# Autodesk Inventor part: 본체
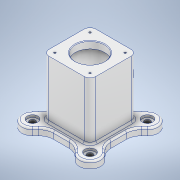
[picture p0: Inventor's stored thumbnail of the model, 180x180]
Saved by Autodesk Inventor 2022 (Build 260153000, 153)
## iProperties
Created: 2022-05
Part Number: 본체
Material: 알루미늄 6061
Document SubType Name: Modeling
Designer: Admin
Mass: 1072.62 g
Surface Area: 876.974 cm^2
Volume: 397.266 cm^3
Density: 2.7 g/cm^3
Appearance: 알루미늄 - 평지
Author: Admin
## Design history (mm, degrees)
sketch "스케치1"
  geometry: L1 (40, 40)-(-40, 40); L2 (-40, 40)-(-40, -40); L3 (-40, -40)-(40, -40); L4 (40, -40)-(40, 40); L5 (40, 40)-(-40, -40); L6 (-40, 40)-(40, -40); 1 further point
  constraints: 12 end point, 2 midpoint, 2 parallel, 1 horizontal, 1 perpendicular
  dimensions: "d0" = 80 distance of L3.end L2.end; "d1" = 80 distance of L2.end L1.end
extrude "돌출1" new body sketch "스케치1" distance "d2" = 110; taper "d3" = 0 deg
sketch "스케치2"
  geometry: L1 (40, 40)-(40, -40) reference; L2 (-40, 40)-(40, 40) reference; L3 (-40, -40)-(-40, 40) reference; L4 (40, -40)-(-40, -40) reference; L5 (-104.238, 0)-(104.238, 0) reference; L6 (0, -104.238)-(0, 104.238) reference; L7 (-23.544, 49)-(23.544, 49); L8 (49, 23.544)-(49, -23.544); L9 (23.544, -49)-(-23.544, -49); L10 (-49, -23.544)-(-49, 23.544); L11 (-49, 49)-(49, -49); L12 (49, 49)-(-49, -49); L13 (-49, 49)-(49, -49); L14 (-49, -49)-(49, 49); L15 (49, 23.544)-(61.728, 36.272); L16 (61.728, -36.272)-(49, -23.544); L17 (36.272, 61.728)-(23.544, 49); L18 (-23.544, 49)-(-36.272, 61.728); L19 (-61.728, 36.272)-(-49, 23.544); L20 (-49, -23.544)-(-61.728, -36.272); L21 (-36.272, -61.728)-(-23.544, -49); L22 (23.544, -49)-(36.272, -61.728); A1 r 18 centre (-49, 49) between (-36.272, 61.728) and (-61.728, 36.272); A2 r 18 centre (49, -49) between (36.272, -61.728) and (61.728, -36.272); A3 r 18 centre (-49, -49) between (-61.728, -36.272) and (-36.272, -61.728); A4 r 18 centre (49, 49) between (61.728, 36.272) and (36.272, 61.728); 1 further point
  constraints: 36 end point, 16 tangent, 12 equal length, 8 point on circle, 4 centre point, 4 midpoint, 1 horizontal, 1 perpendicular, 1 point on line
  dimensions: "d7" = 98 distance of L11.end L12.end; "d8" = 98 distance of L12.start L11.end; "d9" = 36 diameter of A2; "d10" = 36 diameter of A4; "d11" = 49 distance between parallel lines of L6 L8; "d12" = 49 distance between parallel lines of L6 L10; "d13" = 98 distance between parallel lines of L7 L9; "d14" = 49 distance between parallel lines of L7 L5; "d15" = 45 deg angle of L5 L14; "d16" = 45 deg angle of L5 L11
extrude "돌출2" join sketch "스케치2" distance "d17" = 12; taper "d18" = 0 deg
sketch "스케치3"
  geometry: L1 (-61.728, -36.272)-(-49, -23.544) reference; L2 (-49, -23.544)-(-49, 23.544) reference; L3 (-49, 23.544)-(-61.728, 36.272) reference; L4 (-36.272, 61.728)-(-23.544, 49) reference; L5 (-23.544, 49)-(23.544, 49) reference; L6 (23.544, 49)-(36.272, 61.728) reference; L7 (61.728, 36.272)-(49, 23.544) reference; L8 (49, 23.544)-(49, -23.544) reference; L9 (49, -23.544)-(61.728, -36.272) reference; L10 (36.272, -61.728)-(23.544, -49) reference; L11 (23.544, -49)-(-23.544, -49) reference; L12 (-23.544, -49)-(-36.272, -61.728) reference; A1 r 18 centre (-49, 49) between (-36.272, 61.728) and (-61.728, 36.272) reference; A2 r 18 centre (49, 49) between (61.728, 36.272) and (36.272, 61.728) reference; A3 r 18 centre (49, -49) between (36.272, -61.728) and (61.728, -36.272) reference; A4 r 18 centre (-49, -49) between (-61.728, -36.272) and (-36.272, -61.728) reference; 5 further points
  constraints: 4 coincident
hole "구멍1" sketch "스케치3" at (49, 49), (49, -49), (-49, 49), (-49, -49) diameter "d19" = 10; stored, may be unused: countersink angle "d23" = 90 deg, drill point angle "d25" = 118 deg; dims "d20" = 11, "d21" = 18, "d22" = 4, "d24" = 13
sketch "스케치4"
  geometry: L1 (40, -132)-(40, 22) reference; L2 (16.456, -98)-(63.544, -98) reference; C1 r 20 at (40, -49); 1 further point
  constraints: 1 centre point, 1 point on line
  dimensions: "d26" = 40 diameter of C1; "d27" = 49 distance from line of L2 C1.centre
extrude "돌출3" join sketch "스케치4" distance "d28" = 15; taper "d29" = 0 deg
sketch "스케치5"
  geometry: C1 r 20 at (0, 0) reference; C2 r 15 at (0, 0); 1 further point
  constraints: 1 centre point, 1 coincident
  dimensions: "d30" = 30 diameter of C2
extrude "돌출4" cut sketch "스케치5" distance "d31" = 8; taper "d32" = 0 deg
sketch "스케치6"
  geometry: L1 (-22, 0)-(132, 0) reference; L2 (0, -93.8)-(0, 93.8) reference; L3 (110, -40)-(110, 40) reference; L4 (110, -25)-(98, -25); L5 (98, -25)-(98, -35); L6 (98, -35)-(12, -35); L7 (12, -35)-(12, -25); L8 (12, -25)-(0, -25); L9 (0, 23.544)-(0, -23.544) reference; L10 (110, -25)-(110, 0); L11 (110, 0)-(0, 0); L12 (0, 0)-(0, -25); 1 further point
  constraints: 16 end point, 4 point on line, 3 perpendicular, 2 collinear, 1 horizontal, 1 midpoint
  dimensions: "d33" = 70 diameter of L6 L1; "d34" = 50 diameter of L8 L1; "d35" = 86 distance of L5.end L6.end; "d36" = 12 distance of L4.start L4.end
revolve "회전1" sketch "스케치6" stored, may be unused: angle "d37" = 90 deg
sketch "스케치7"
  geometry: C1 r 15 at (0, 0) reference; C2 r 15 at (0, 0) reference; C3 r 12.5 at (0, 0); 1 further point
  constraints: 1 centre point, 1 coincident
  dimensions: "d38" = 25 diameter of C3
extrude "돌출5" cut sketch "스케치7" stored distance "d39" = 8; taper "d40" = 0 deg
fillet "모깎기1" dims "d41" = 3
sketch "스케치8"
  geometry: L1 (0, -98)-(80, -98) reference; L2 (80, -98)-(80, 0) reference; L3 (0, 0)-(80, 0) reference; L4 (0, -98)-(0, 0) reference; L5 (40, -132)-(40, 22) reference; C1 r 20 at (40, -49) reference; 2 further points
  constraints: 1 point on line, 1 other
  dimensions: "d42" = 10 distance from line of L3 point (40, -10)
feature "엠보싱1" sketch "스케치8" dims "d0" = 80, "d1" = 80, "d7" = 98, "d8" = 98, "d9" = 36, "d10" = 36, "d11" = 49, "d12" = 49, "d13" = 98, "d14" = 49, "d15" = 45 deg, "d16" = 45 deg, "d43" = 0.5, "d44" = 0
chamfer "모따기1" distance "d45" = 1; stored, may be unused: second distance "d46" = 2, angle "d47" = 45 deg
chamfer "모따기2" distance "d48" = 1; stored, may be unused: second distance "d49" = 2, angle "d50" = 45 deg
chamfer "모따기3" distance "d51" = 1; stored, may be unused: second distance "d52" = 2, angle "d53" = 45 deg
fillet "모깎기2" dims "d54" = 10
fillet "모깎기3" dims "d55" = 3
fillet "모깎기6" dims "d76" = 25
fillet "모깎기7" dims "d77" = 3
sketch "스케치11"
  geometry: L1 (-30, -30)-(30, -30); L2 (30, -30)-(30, 30); L3 (30, 30)-(-30, 30); L4 (-30, 30)-(-30, -30); L5 (-30, -30)-(30, 30); L6 (30, -30)-(-30, 30); 5 further points
  constraints: 12 end point, 4 coincident, 2 midpoint, 2 parallel, 1 horizontal, 1 perpendicular
  dimensions: "d78" = 60 distance of L3.end L2.end; "d79" = 60 distance of L2.end L1.end
hole "구멍4" sketch "스케치11" at (-30, 30), (30, 30), (30, -30), (-30, -30) diameter "d80" = 3.242; stored, may be unused: countersink angle "d84" = 90 deg, drill point angle "d86" = 118 deg; dims "d81" = 8, "d82" = 4, "d83" = 2, "d85" = 10
sketch "스케치12"
  geometry: L1 (30, 30)-(-30, 30); L2 (-30, 30)-(-30, -30); L3 (-30, -30)-(30, -30); L4 (30, -30)-(30, 30); L5 (30, 30)-(-30, -30); L6 (-30, 30)-(30, -30); C1 r 1.621 at (30, -30) reference; C2 r 1.621 at (-30, -30) reference; C3 r 1.621 at (-30, 30) reference; C4 r 1.621 at (30, 30) reference; 5 further points
  constraints: 12 end point, 4 coincident, 2 midpoint, 2 parallel, 1 horizontal, 1 perpendicular
  dimensions: "d87" = 60 distance of L3.end L2.end; "d88" = 60 distance of L2.end L1.end
hole "구멍5" sketch "스케치12" at (30, -30), (-30, -30), (-30, 30), (30, 30) diameter "d89" = 3.242; stored, may be unused: countersink angle "d93" = 90 deg, drill point angle "d95" = 118 deg; dims "d90" = 8, "d91" = 4, "d92" = 2, "d94" = 10
node "솔리드1"
node "투영된 루프1"
node "투영된 루프2"
node "투영된 루프3"
node "투영된 루프4"
node "투영된 루프5"
feature "A9D066F2-1C7D-4E18-AEED-F7BC21143FA4" dims "d19" = 10, "d20" = 11, "d21" = 18, "d22" = 4, "d23" = 90 deg, "d24" = 13, "d25" = 118 deg
